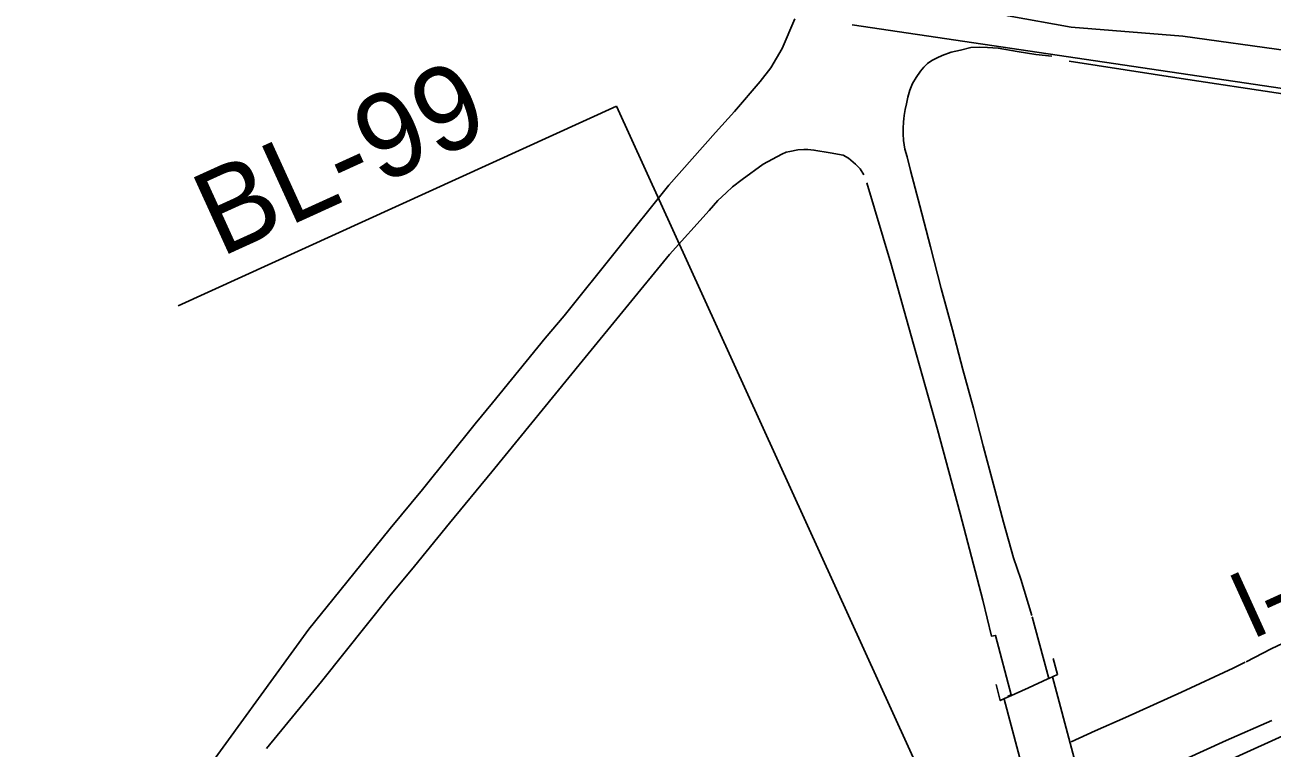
# Model space of a CAD drawing. Extents: x 2243531 to 2252747, y 658714 to 667210.
# Drawn here: x 2247065 to 2247806, y 662839 to 663269 of the extents above; entities that cross this region are included whole.
import ezdxf

# ---------------------------------------------------------------- set-up
doc = ezdxf.new("R2010")
doc.units = 0
for name, color, linetype in [('CTL NGS Horizontal CELL', 7, 'Continuous'), ('CTL Sheet Text', 7, 'Continuous'), ('CTL Supplemental Horizontal and Vertical Text', 7, 'Continuous'), ('Exist Horizontal Alignment Point', 7, 'Continuous'), ('Exist Roads Curbs', 7, 'Continuous'), ('Exist Roads EOP', 7, 'Continuous'), ('Exist Roads EOP Text', 7, 'Continuous'), ('Exist Structure Major Bridge WW', 7, 'Continuous'), ('Exist Structure Major Deck Tunnel Box Culvert', 7, 'Continuous'), ('Prop Horizontal Alignment', 7, 'Continuous')]:
    doc.layers.add(name, color=color, linetype=linetype)

msp = doc.modelspace()

# ---------------------------------------------------------------- linework, layer by layer
at = {"layer": 'CTL NGS Horizontal CELL'}
for p, q in [((2247416.43, 663220.85), (2247155.92, 663102.13)), ((2247624.95, 662763.25), (2247416.43, 663220.85))]:
    msp.add_line(p, q, dxfattribs=at)
at = {"layer": 'Exist Horizontal Alignment Point'}
msp.add_line((2247562.57, 663268.36), (2247562.57, 663268.36), dxfattribs=at)
at = {"layer": 'Exist Roads Curbs'}
msp.add_lwpolyline([(2247673.38, 662880.7), (2247670.61, 662891), (2247667.54, 662902.61), (2247663.6, 662917.3)], dxfattribs=at)
at = {"layer": 'Exist Roads EOP'}
for points in [[(2247686.65, 663267.85), (2247649.21, 663274.71), (2247614.62, 663285.85), (2247600.35, 663293.65), (2247584.79, 663303.09), (2247571.97, 663315.62), (2247562.04, 663330.85), (2247558.49, 663338.65)], [(2247060.47, 662690.79), (2247089.2, 662724.04), (2247097.86, 662734.77), (2247110.64, 662749.29), (2247118.53, 662759.15), (2247124.02, 662765.83), (2247131.3, 662774.65), (2247143.07, 662789), (2247164.81, 662815.2), (2247233.54, 662909.92), (2247252.03, 662932.82), (2247281.84, 662969.79), (2247301.09, 662993.04), (2247332.47, 663032.01), (2247342.66, 663044.55), (2247374.02, 663082.95), (2247385.31, 663096.34), (2247447.6, 663174.05), (2247475.37, 663205.35), (2247486.53, 663217.81), (2247501.84, 663235.65), (2247508.17, 663243.82), (2247515.04, 663255.14), (2247522.47, 663272.91)], [(2248082.73, 663206.66), (2248049.94, 663212.37), (2248007.96, 663224.19), (2247962.67, 663231.65), (2247875.48, 663244.42), (2247816.01, 663253.81), (2247753.12, 663262.61), (2247686.65, 663267.85)], [(2247663.36, 662918.14), (2247656.77, 662939.58), (2247652.46, 662952.28), (2247646.51, 662973.52), (2247640.54, 662995.97), (2247634.4, 663018.91), (2247628.62, 663041.28), (2247622.41, 663064.35), (2247616.22, 663087.93), (2247609.5, 663112.61), (2247603.05, 663137.33), (2247596.69, 663161.59), (2247591.18, 663182.72), (2247589.21, 663190.76), (2247587.94, 663195.36), (2247587.02, 663200.57), (2247586.8, 663204.44), (2247586.85, 663207.87), (2247587.09, 663211.34), (2247587.47, 663215.29), (2247588.02, 663219.01), (2247588.86, 663222.42), (2247589.67, 663226.33), (2247590.84, 663230.45), (2247592.47, 663234.41), (2247594.65, 663238.04), (2247597.15, 663241.7), (2247599.15, 663244.09), (2247601.38, 663246.27), (2247604, 663248.11), (2247607.02, 663249.76), (2247610.08, 663251.12), (2247615.41, 663252.96), (2247620.89, 663254.26), (2247627.09, 663255.76), (2247632.22, 663256.1), (2247636.95, 663255.89), (2247643.3, 663255.45), (2247654.71, 663253.47), (2247665.79, 663251.64), (2247675.2, 663250.58)], [(2248058.86, 663190.49), (2248005.4, 663198.57), (2247962.11, 663205.25), (2247877.39, 663218.37), (2247812.6, 663228.19), (2247752.09, 663237.38), (2247685.58, 663247.72)], [(2247663.36, 662918.14), (2247656.77, 662939.58), (2247652.46, 662952.28), (2247646.51, 662973.52), (2247640.54, 662995.97), (2247634.4, 663018.91), (2247628.62, 663041.28), (2247622.41, 663064.35), (2247616.22, 663087.93), (2247609.5, 663112.61), (2247603.05, 663137.33), (2247596.69, 663161.59), (2247591.18, 663182.72), (2247589.21, 663190.76), (2247587.94, 663195.36), (2247587.02, 663200.57), (2247586.8, 663204.44), (2247586.85, 663207.87), (2247587.09, 663211.34), (2247587.21, 663213.59)], [(2247563.52, 663180.19), (2247561.39, 663183.74), (2247558.51, 663186.51), (2247554.47, 663189.99), (2247551.15, 663191.81), (2247543.51, 663193.1), (2247533.78, 663194.82), (2247530.18, 663195.23), (2247527.79, 663195.26), (2247524.28, 663195.03), (2247519.43, 663193.98), (2247517.39, 663193.51), (2247514.81, 663192.44), (2247503.62, 663186.53), (2247491.09, 663177.26), (2247485.47, 663173), (2247481.62, 663169.46), (2247476.79, 663164.86), (2247471.5, 663158.89), (2247447.92, 663132.7), (2247396.11, 663069.28), (2247342.39, 663003.57), (2247317.18, 662973.02), (2247296.33, 662947.4), (2247281.78, 662929.71), (2247241.05, 662878.88), (2247208.39, 662839.03)], [(2247565.27, 663175.36), (2247579.56, 663127.53), (2247592.96, 663079.39), (2247607.21, 663028.74), (2247620.83, 662978.68), (2247634.17, 662927.28), (2247639.38, 662905.79), (2247641.74, 662906.25), (2247651.17, 662870.99), (2247649.12, 662870.11)], [(2247790.71, 662890.62), (2247805.57, 662898.29), (2247836.78, 662912.86), (2247861.63, 662923.16), (2247885.32, 662933.83), (2247909.61, 662945.06), (2247935.04, 662956.66), (2247966.34, 662970.9), (2247994.49, 662983.87), (2248025.59, 662998.19), (2248058.08, 663012.97), (2248088.08, 663026.44), (2248119.82, 663041.08), (2248150.21, 663054.44), (2248181.1, 663069.6), (2248218.38, 663087.19), (2248245.39, 663099.49), (2248287.88, 663118.8), (2248325.22, 663134.87), (2248357.59, 663149.14), (2248375.51, 663157.12), (2248384.78, 663161.44)], [(2247686.67, 662842.94), (2247701.01, 662849.42), (2247718.96, 662857.46), (2247752.37, 662872.57), (2247783, 662886.74), (2247790.21, 662890.4)], [(2247806.05, 662855.64), (2247778.96, 662843.76), (2247718.06, 662815.97), (2247697.14, 662806.43)]]:
    msp.add_lwpolyline(points, dxfattribs=at)
at = {"layer": 'Exist Structure Major Bridge WW'}
msp.add_lwpolyline([(2247676.02, 662892.45), (2247678.65, 662882.93), (2247673.42, 662880.55), (2247672.97, 662880.34), (2247661.37, 662875.07), (2247649.53, 662869.69), (2247648.98, 662869.45), (2247644.57, 662867.44), (2247642.11, 662877.01)], dxfattribs=at)
at = {"layer": 'Exist Structure Major Deck Tunnel Box Culvert'}
for points in [[(2247675.67, 662881.54), (2247721.67, 662708.9)], [(2247692.64, 662696), (2247646.91, 662868.42)]]:
    msp.add_lwpolyline(points, dxfattribs=at)
at = {"layer": 'Prop Horizontal Alignment'}
for p, q in [((2247500.8, 662705.02), (2249793.08, 663746.29)), ((2248096.71, 663189.45), (2247556.64, 663269.24))]:
    msp.add_line(p, q, dxfattribs=at)

# ---------------------------------------------------------------- texts
at = {"layer": 'CTL Sheet Text'}
msp.add_text('4               I-3318BB-GPS4      664304.4820     2250952.4290           157.09         45+89.29        114.61 RT', height=40, rotation=24.49794, dxfattribs=at).set_placement((2244816.55, 662604.74))
at = {"layer": 'CTL Supplemental Horizontal and Vertical Text'}
msp.add_text('BL-99', height=49.999, rotation=24.49794, dxfattribs=at).set_placement((2247180.97, 663130.85))
at = {"layer": 'Exist Roads EOP Text'}
msp.add_text('I-95 SBL', height=40, rotation=24.46002, dxfattribs=at).set_placement((2247793.54, 662903.33))

doc.saveas('drawing.dxf')
